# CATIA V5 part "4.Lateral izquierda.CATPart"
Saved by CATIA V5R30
Part number: 4.Lateral izquierda
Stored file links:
  C:\Users\valen\Desktop\Estandar CubeSat - Programa AVES-20220531T050024Z-001\Estandar CubeSat - Programa AVES\3D - MODELS\CATIA\4.Lateral izquierda.CATPart

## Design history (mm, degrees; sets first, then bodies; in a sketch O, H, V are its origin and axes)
Set1
  Point1 "Point.1": stored without definition
Body1 "Sólido1" (main body)
  Solid1: solid without history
